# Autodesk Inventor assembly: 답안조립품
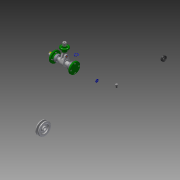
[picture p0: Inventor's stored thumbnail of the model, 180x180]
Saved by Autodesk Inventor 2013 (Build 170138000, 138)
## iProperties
Created: 2016-01
Part Number: 답안조립품
Document SubType Name: Assembly
Designer: Administrator
Author: Administrator
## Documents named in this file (19)
- C:\Users\Administrator\Desktop\460127V1014\답안조립품.iam
- C:\Users\Administrator\Desktop\460127V1014\본체.ipt
- C:\Users\Administrator\Desktop\460127V1014\V-벨트풀리.ipt
- C:\Users\Administrator\Desktop\460127V1014\고정핀.ipt
- C:\Users\Administrator\Desktop\460127V1014\뒤커버.ipt
- C:\Users\Administrator\Desktop\460127V1014\링크.ipt
- C:\Users\Administrator\Desktop\460127V1014\멈춤링 6 x 5.ipt
- C:\Users\Administrator\Desktop\460127V1014\멈춤링 15 x 1.ipt
- C:\Users\Administrator\Desktop\460127V1014\베어링 15 x 35 x 11.ipt
- C:\Users\Administrator\Desktop\460127V1014\볼트 M3 x 8.ipt
- C:\Users\Administrator\Desktop\460127V1014\볼트 M4 x 10.ipt
- C:\Users\Administrator\Desktop\460127V1014\볼트 M6 x 12.ipt
- C:\Users\Administrator\Desktop\460127V1014\상부부시.ipt
- C:\Users\Administrator\Desktop\460127V1014\슬라이드바.ipt
- C:\Users\Administrator\Desktop\460127V1014\앞커버.ipt
- C:\Users\Administrator\Desktop\460127V1014\오일실 15 25 7.ipt
- C:\Users\Administrator\Desktop\460127V1014\와셔.ipt
- C:\Users\Administrator\Desktop\460127V1014\키 5 x 5 x 14.ipt
- C:\Users\Administrator\Desktop\460127V1014\편심축.ipt
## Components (15 placed, 5 different names)
1. V-벨트풀리:1
2. 고정핀:1
3. ISO 4018 M6 x 12:1
4. ISO 4762 M4 x 10:1
5. ISO 4762 M4 x 10:3
6. ISO 4762 M4 x 10:4
7. ISO 4762 M4 x 10:5
8. ISO 4762 M4 x 10:2
9. ISO 4762 M4 x 10:6
10. ISO 4762 M4 x 10:7
11. ISO 4762 M4 x 10:8
12. ISO 4762 M3 x 8:1
13. ISO 4762 M3 x 8:2
14. ISO 4762 M3 x 8:3
15. ISO 4762 M3 x 8:4
